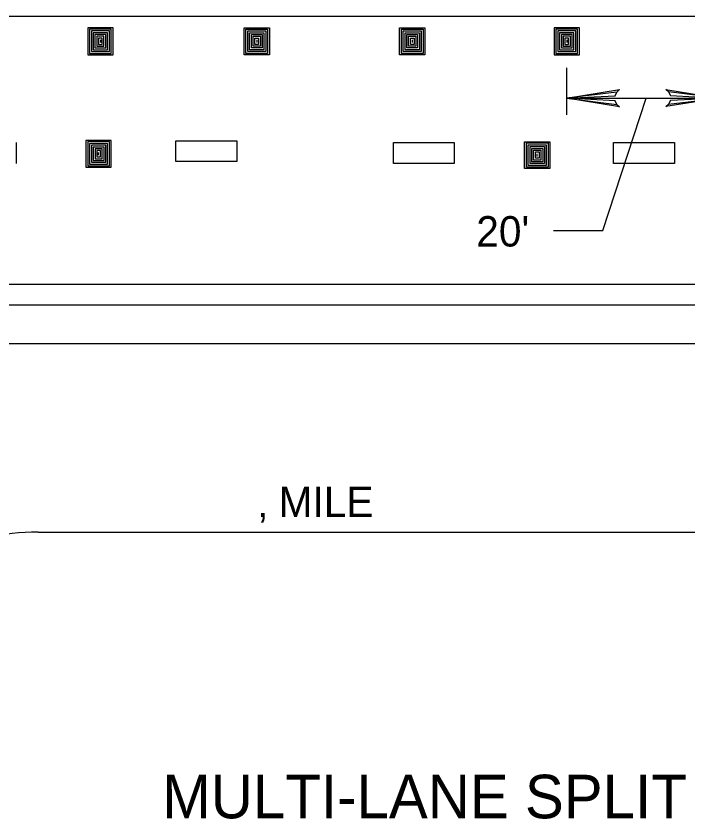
# Model space of a CAD drawing. Extents: x 639362 to 641108, y 298458 to 299646.
# Drawn here: x 639586 to 639652.3, y 299148 to 299227.2 of the extents above; entities that cross this region are included whole.
import ezdxf

# ---------------------------------------------------------------- set-up
doc = ezdxf.new("R2010")
doc.units = 0
doc.layers.add('2', color=7, linetype='Continuous')

msp = doc.modelspace()

# ---------------------------------------------------------------- linework, layer by layer
at = {"layer": '2'}
for p, q in [((639583.053, 299227.209), (639672.738, 299227.209)), ((639595.54, 299226.054), (639593.043, 299226.054)), ((639593.043, 299226.054), (639593.043, 299223.4)), ((639595.355, 299225.921), (639593.226, 299225.921)), ((639593.226, 299225.921), (639593.226, 299223.527)), ((639595.175, 299225.745), (639593.401, 299225.745)), ((639593.401, 299225.745), (639593.401, 299223.706)), ((639594.998, 299225.567), (639593.581, 299225.567)), ((639593.581, 299225.567), (639593.581, 299223.881)), ((639594.998, 299223.881), (639594.998, 299225.567)), ((639595.175, 299223.706), (639595.175, 299225.745)), ((639595.355, 299223.527), (639595.355, 299225.921)), ((639595.54, 299223.4), (639595.54, 299226.054)), ((639608.472, 299226.054), (639610.968, 299226.054)), ((639608.472, 299223.4), (639608.472, 299226.054)), ((639608.656, 299225.921), (639610.785, 299225.921)), ((639608.656, 299223.527), (639608.656, 299225.921)), ((639608.836, 299225.745), (639610.61, 299225.745)), ((639608.836, 299223.706), (639608.836, 299225.745)), ((639609.013, 299225.567), (639610.43, 299225.567)), ((639609.013, 299223.881), (639609.013, 299225.567)), ((639610.43, 299225.567), (639610.43, 299223.881)), ((639610.61, 299225.745), (639610.61, 299223.706)), ((639610.785, 299225.921), (639610.785, 299223.527)), ((639610.968, 299226.054), (639610.968, 299223.4)), ((639623.81, 299226.054), (639626.306, 299226.054)), ((639623.81, 299223.4), (639623.81, 299226.054)), ((639623.995, 299225.921), (639626.124, 299225.921)), ((639623.995, 299223.527), (639623.995, 299225.921)), ((639624.174, 299225.745), (639625.948, 299225.745)), ((639624.174, 299223.706), (639624.174, 299225.745)), ((639624.351, 299225.567), (639625.768, 299225.567)), ((639624.351, 299223.881), (639624.351, 299225.567)), ((639625.768, 299225.567), (639625.768, 299223.881)), ((639625.948, 299225.745), (639625.948, 299223.706)), ((639626.124, 299225.921), (639626.124, 299223.527)), ((639626.306, 299226.054), (639626.306, 299223.4)), ((639641.554, 299226.054), (639639.058, 299226.054)), ((639639.058, 299226.054), (639639.058, 299223.4)), ((639641.369, 299225.921), (639639.24, 299225.921)), ((639639.24, 299225.921), (639639.24, 299223.527)), ((639641.19, 299225.745), (639639.416, 299225.745)), ((639639.416, 299225.745), (639639.416, 299223.706)), ((639641.013, 299225.567), (639639.596, 299225.567)), ((639639.596, 299225.567), (639639.596, 299223.881)), ((639641.013, 299223.881), (639641.013, 299225.567)), ((639641.19, 299223.706), (639641.19, 299225.745)), ((639641.369, 299223.527), (639641.369, 299225.921)), ((639641.554, 299223.4), (639641.554, 299226.054)), ((639594.822, 299225.39), (639593.758, 299225.39)), ((639593.758, 299225.39), (639593.758, 299224.059)), ((639593.934, 299225.212), (639593.934, 299224.236)), ((639594.646, 299225.212), (639593.934, 299225.212)), ((639594.466, 299225.035), (639594.111, 299225.035)), ((639594.111, 299225.035), (639594.111, 299224.414)), ((639594.29, 299224.858), (639594.29, 299224.591)), ((639594.466, 299224.414), (639594.466, 299225.035)), ((639594.646, 299224.236), (639594.646, 299225.212)), ((639594.822, 299224.059), (639594.822, 299225.39)), ((639609.189, 299225.39), (639610.253, 299225.39)), ((639609.189, 299224.059), (639609.189, 299225.39)), ((639609.366, 299224.236), (639609.366, 299225.212)), ((639609.366, 299225.212), (639610.078, 299225.212)), ((639609.545, 299225.035), (639609.901, 299225.035)), ((639609.545, 299224.414), (639609.545, 299225.035)), ((639609.721, 299224.858), (639609.721, 299224.591)), ((639609.901, 299225.035), (639609.901, 299224.414)), ((639610.078, 299225.212), (639610.078, 299224.236)), ((639610.253, 299225.39), (639610.253, 299224.059)), ((639624.527, 299225.39), (639625.591, 299225.39)), ((639624.527, 299224.059), (639624.527, 299225.39)), ((639624.704, 299224.236), (639624.704, 299225.212)), ((639624.704, 299225.212), (639625.416, 299225.212)), ((639624.883, 299225.035), (639625.239, 299225.035)), ((639624.883, 299224.414), (639624.883, 299225.035)), ((639625.059, 299224.858), (639625.059, 299224.591)), ((639625.239, 299225.035), (639625.239, 299224.414)), ((639625.416, 299225.212), (639625.416, 299224.236)), ((639625.591, 299225.39), (639625.591, 299224.059)), ((639640.837, 299225.39), (639639.773, 299225.39)), ((639639.773, 299225.39), (639639.773, 299224.059)), ((639639.948, 299225.212), (639639.948, 299224.236)), ((639640.66, 299225.212), (639639.948, 299225.212)), ((639640.481, 299225.035), (639640.125, 299225.035)), ((639640.125, 299225.035), (639640.125, 299224.414)), ((639640.305, 299224.858), (639640.305, 299224.591)), ((639640.481, 299224.414), (639640.481, 299225.035)), ((639640.66, 299224.236), (639640.66, 299225.212)), ((639640.837, 299224.059), (639640.837, 299225.39)), ((639593.758, 299224.059), (639594.822, 299224.059)), ((639593.934, 299224.236), (639594.646, 299224.236)), ((639594.111, 299224.414), (639594.466, 299224.414)), ((639610.253, 299224.059), (639609.189, 299224.059)), ((639610.078, 299224.236), (639609.366, 299224.236)), ((639609.901, 299224.414), (639609.545, 299224.414)), ((639625.591, 299224.059), (639624.527, 299224.059)), ((639625.416, 299224.236), (639624.704, 299224.236)), ((639625.239, 299224.414), (639624.883, 299224.414)), ((639639.773, 299224.059), (639640.837, 299224.059)), ((639639.948, 299224.236), (639640.66, 299224.236)), ((639640.125, 299224.414), (639640.481, 299224.414)), ((639593.043, 299223.4), (639595.54, 299223.4)), ((639593.226, 299223.527), (639595.355, 299223.527)), ((639593.401, 299223.706), (639595.175, 299223.706)), ((639593.581, 299223.881), (639594.998, 299223.881)), ((639610.968, 299223.4), (639608.472, 299223.4)), ((639610.785, 299223.527), (639608.656, 299223.527)), ((639610.61, 299223.706), (639608.836, 299223.706)), ((639610.43, 299223.881), (639609.013, 299223.881)), ((639626.306, 299223.4), (639623.81, 299223.4)), ((639626.124, 299223.527), (639623.995, 299223.527)), ((639625.948, 299223.706), (639624.174, 299223.706)), ((639625.768, 299223.881), (639624.351, 299223.881)), ((639639.058, 299223.4), (639641.554, 299223.4)), ((639639.24, 299223.527), (639641.369, 299223.527)), ((639639.416, 299223.706), (639641.19, 299223.706)), ((639639.596, 299223.881), (639641.013, 299223.881)), ((639640.264, 299222.104), (639640.264, 299217.479)), ((639640.264, 299219.116), (639655.337, 299219.116)), ((639643.862, 299206.072), (639648.125, 299219.116)), ((639585.971, 299214.725), (639585.971, 299212.661)), ((639595.365, 299214.951), (639592.869, 299214.951)), ((639592.869, 299214.951), (639592.869, 299212.297)), ((639595.183, 299214.825), (639593.054, 299214.825)), ((639593.054, 299214.825), (639593.054, 299212.43)), ((639595.007, 299214.645), (639593.233, 299214.645)), ((639593.233, 299214.645), (639593.233, 299212.606)), ((639594.827, 299214.471), (639593.41, 299214.471)), ((639593.41, 299214.471), (639593.41, 299212.784)), ((639594.827, 299212.784), (639594.827, 299214.471)), ((639595.007, 299212.606), (639595.007, 299214.645)), ((639595.183, 299212.43), (639595.183, 299214.825)), ((639595.365, 299212.297), (639595.365, 299214.951)), ((639601.741, 299212.848), (639601.741, 299214.913)), ((639601.741, 299214.913), (639607.754, 299214.913)), ((639607.754, 299214.913), (639607.754, 299212.848)), ((639623.195, 299212.661), (639623.195, 299214.725)), ((639623.195, 299214.725), (639629.208, 299214.725)), ((639629.208, 299214.725), (639629.208, 299212.661)), ((639636.149, 299212.165), (639636.149, 299214.819)), ((639636.149, 299214.819), (639638.645, 299214.819)), ((639636.331, 299212.298), (639636.331, 299214.692)), ((639636.331, 299214.692), (639638.46, 299214.692)), ((639636.507, 299212.474), (639636.507, 299214.513)), ((639636.507, 299214.513), (639638.281, 299214.513)), ((639638.281, 299214.513), (639638.281, 299212.474)), ((639638.46, 299214.692), (639638.46, 299212.298)), ((639638.645, 299214.819), (639638.645, 299212.165)), ((639644.915, 299212.661), (639644.915, 299214.725)), ((639644.915, 299214.725), (639650.929, 299214.725)), ((639650.929, 299214.725), (639650.929, 299212.661)), ((639594.65, 299214.292), (639593.586, 299214.292)), ((639593.586, 299214.292), (639593.586, 299212.961)), ((639594.475, 299214.115), (639593.763, 299214.115)), ((639593.763, 299214.115), (639593.763, 299213.139)), ((639594.298, 299213.937), (639593.942, 299213.937)), ((639593.942, 299213.937), (639593.942, 299213.316)), ((639594.118, 299213.493), (639594.118, 299213.76)), ((639594.298, 299213.316), (639594.298, 299213.937)), ((639594.475, 299213.139), (639594.475, 299214.115)), ((639594.65, 299212.961), (639594.65, 299214.292)), ((639636.687, 299212.652), (639636.687, 299214.338)), ((639636.687, 299214.338), (639638.104, 299214.338)), ((639636.864, 299212.829), (639636.864, 299214.16)), ((639636.864, 299214.16), (639637.928, 299214.16)), ((639637.039, 299213.007), (639637.039, 299213.983)), ((639637.039, 299213.983), (639637.751, 299213.983)), ((639637.216, 299213.184), (639637.216, 299213.805)), ((639637.216, 299213.805), (639637.572, 299213.805)), ((639637.572, 299213.805), (639637.572, 299213.184)), ((639637.751, 299213.983), (639637.751, 299213.007)), ((639637.928, 299214.16), (639637.928, 299212.829)), ((639638.104, 299214.338), (639638.104, 299212.652)), ((639593.586, 299212.961), (639594.65, 299212.961)), ((639593.763, 299213.139), (639594.475, 299213.139)), ((639593.942, 299213.316), (639594.298, 299213.316)), ((639637.751, 299213.007), (639637.039, 299213.007)), ((639637.572, 299213.184), (639637.216, 299213.184)), ((639637.396, 299213.361), (639637.396, 299213.628)), ((639592.869, 299212.297), (639595.365, 299212.297)), ((639593.054, 299212.43), (639595.183, 299212.43)), ((639593.233, 299212.606), (639595.007, 299212.606)), ((639593.41, 299212.784), (639594.827, 299212.784)), ((639607.754, 299212.848), (639601.741, 299212.848)), ((639629.208, 299212.661), (639623.195, 299212.661)), ((639638.645, 299212.165), (639636.149, 299212.165)), ((639638.46, 299212.298), (639636.331, 299212.298)), ((639638.281, 299212.474), (639636.507, 299212.474)), ((639638.104, 299212.652), (639636.687, 299212.652)), ((639637.928, 299212.829), (639636.864, 299212.829)), ((639650.929, 299212.661), (639644.915, 299212.661)), ((639639.011, 299206.072), (639643.862, 299206.072)), ((639583.095, 299200.773), (639789.679, 299200.773)), ((639789.679, 299198.709), (639583.098, 299198.709)), ((639583.095, 299194.923), (639789.679, 299194.923)), ((639588.146, 299176.289), (639669.771, 299176.289))]:
    msp.add_line(p, q, dxfattribs=at)
for points in [[(639645.258, 299218.489), (639645.072, 299218.851), (639640.264, 299219.116), (639645.258, 299218.489), (639645.514, 299218.27), (639640.264, 299219.116), (639645.068, 299219.354), (639645.244, 299219.712), (639640.264, 299219.116), (639645.514, 299219.951), (639645.244, 299219.712)], [(639650.342, 299219.743), (639650.528, 299219.382), (639655.337, 299219.116), (639650.342, 299219.743), (639650.086, 299219.962), (639655.337, 299219.116), (639650.532, 299218.879), (639650.357, 299218.521), (639655.337, 299219.116), (639650.086, 299218.282), (639650.357, 299218.521)]]:
    msp.add_lwpolyline(points, dxfattribs=at)
msp.add_arc((639588.173, 299155.144), 21.171, 90.07158, 117.92865, dxfattribs=at)

# ---------------------------------------------------------------- texts
for s, height, p in [("20'", 3, (639631.374, 299204.476)), ('‚ MILE', 3, (639609.866, 299177.79)), ('MULTI-LANE SPLIT', 4.3, (639600.392, 299148.077))]:
    msp.add_text(s, height=height, dxfattribs=at).set_placement(p)

doc.saveas('drawing.dxf')
